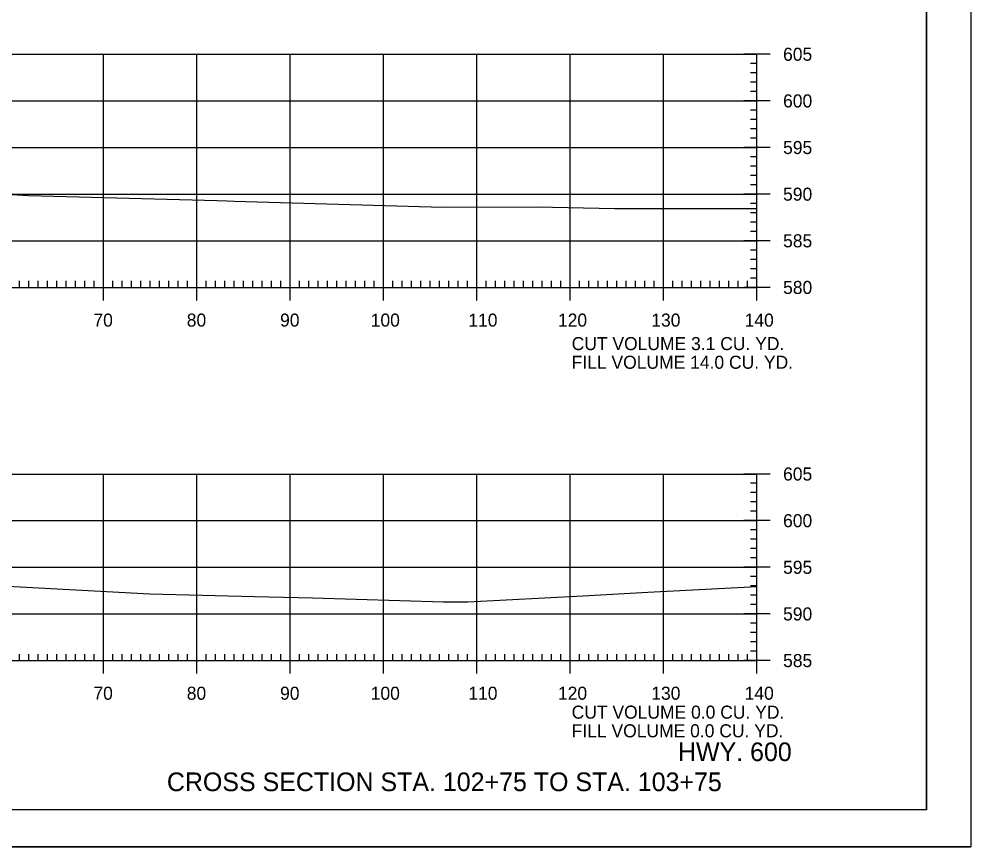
# Model space of a CAD drawing. Extents: x 961436 to 1372525, y 380079 to 2027791.
# Drawn here: x 1371255.8 to 1371357.8, y 380109.1 to 380197.8 of the extents above; entities that cross this region are included whole.
import ezdxf

# ---------------------------------------------------------------- set-up
doc = ezdxf.new("R2010")
doc.units = 0
for name, color, linetype in [('R_Axis', 7, 'Continuous'), ('R_Axis Annot', 7, 'Continuous'), ('R_Border', 7, 'Continuous'), ('R_Draft', 7, 'Continuous'), ('R_Exist Surface', 7, 'Continuous'), ('R_Grid', 7, 'Continuous'), ('R_No Plot', 7, 'Continuous')]:
    doc.layers.add(name, color=color, linetype=linetype)

msp = doc.modelspace()

# ---------------------------------------------------------------- linework, layer by layer
at = {"layer": 'R_Axis'}
for p, q in [((1371336.28, 380194.06), (1371333.48, 380194.06)), ((1371334.88, 380169.06), (1371334.88, 380194.06)), ((1371334.88, 380193.06), (1371334.18, 380193.06)), ((1371334.88, 380192.06), (1371334.18, 380192.06)), ((1371334.88, 380191.06), (1371334.18, 380191.06)), ((1371334.88, 380190.06), (1371334.18, 380190.06)), ((1371336.28, 380189.06), (1371333.48, 380189.06)), ((1371334.88, 380188.06), (1371334.18, 380188.06)), ((1371334.88, 380187.06), (1371334.18, 380187.06)), ((1371334.88, 380186.06), (1371334.18, 380186.06)), ((1371334.88, 380185.06), (1371334.18, 380185.06)), ((1371336.28, 380184.06), (1371333.48, 380184.06)), ((1371334.88, 380183.06), (1371334.18, 380183.06)), ((1371334.88, 380182.06), (1371334.18, 380182.06)), ((1371334.88, 380181.06), (1371334.18, 380181.06)), ((1371334.88, 380180.06), (1371334.18, 380180.06)), ((1371336.28, 380179.06), (1371333.48, 380179.06)), ((1371334.88, 380178.06), (1371334.18, 380178.06)), ((1371334.88, 380177.06), (1371334.18, 380177.06)), ((1371334.88, 380176.06), (1371334.18, 380176.06)), ((1371334.88, 380175.06), (1371334.18, 380175.06)), ((1371336.28, 380174.06), (1371333.48, 380174.06)), ((1371334.88, 380173.06), (1371334.18, 380173.06)), ((1371334.88, 380172.06), (1371334.18, 380172.06)), ((1371264.88, 380167.66), (1371264.88, 380170.46)), ((1371274.88, 380167.66), (1371274.88, 380170.46)), ((1371284.88, 380167.66), (1371284.88, 380170.46)), ((1371294.88, 380167.66), (1371294.88, 380170.46)), ((1371304.88, 380167.66), (1371304.88, 380170.46)), ((1371314.88, 380167.66), (1371314.88, 380170.46)), ((1371324.88, 380167.66), (1371324.88, 380170.46)), ((1371334.88, 380171.06), (1371334.18, 380171.06)), ((1371334.88, 380170.06), (1371334.18, 380170.06)), ((1371334.88, 380167.66), (1371334.88, 380170.46)), ((1371054.88, 380169.06), (1371334.88, 380169.06)), ((1371255.88, 380169.06), (1371255.88, 380169.76)), ((1371256.88, 380169.06), (1371256.88, 380169.76)), ((1371257.88, 380169.06), (1371257.88, 380169.76)), ((1371258.88, 380169.06), (1371258.88, 380169.76)), ((1371259.88, 380169.06), (1371259.88, 380169.76)), ((1371260.88, 380169.06), (1371260.88, 380169.76)), ((1371261.88, 380169.06), (1371261.88, 380169.76)), ((1371262.88, 380169.06), (1371262.88, 380169.76)), ((1371263.88, 380169.06), (1371263.88, 380169.76)), ((1371265.88, 380169.06), (1371265.88, 380169.76)), ((1371266.88, 380169.06), (1371266.88, 380169.76)), ((1371267.88, 380169.06), (1371267.88, 380169.76)), ((1371268.88, 380169.06), (1371268.88, 380169.76)), ((1371269.88, 380169.06), (1371269.88, 380169.76)), ((1371270.88, 380169.06), (1371270.88, 380169.76)), ((1371271.88, 380169.06), (1371271.88, 380169.76)), ((1371272.88, 380169.06), (1371272.88, 380169.76)), ((1371273.88, 380169.06), (1371273.88, 380169.76)), ((1371275.88, 380169.06), (1371275.88, 380169.76)), ((1371276.88, 380169.06), (1371276.88, 380169.76)), ((1371277.88, 380169.06), (1371277.88, 380169.76)), ((1371278.88, 380169.06), (1371278.88, 380169.76)), ((1371279.88, 380169.06), (1371279.88, 380169.76)), ((1371280.88, 380169.06), (1371280.88, 380169.76)), ((1371281.88, 380169.06), (1371281.88, 380169.76)), ((1371282.88, 380169.06), (1371282.88, 380169.76)), ((1371283.88, 380169.06), (1371283.88, 380169.76)), ((1371285.88, 380169.06), (1371285.88, 380169.76)), ((1371286.88, 380169.06), (1371286.88, 380169.76)), ((1371287.88, 380169.06), (1371287.88, 380169.76)), ((1371288.88, 380169.06), (1371288.88, 380169.76)), ((1371289.88, 380169.06), (1371289.88, 380169.76)), ((1371290.88, 380169.06), (1371290.88, 380169.76)), ((1371291.88, 380169.06), (1371291.88, 380169.76)), ((1371292.88, 380169.06), (1371292.88, 380169.76)), ((1371293.88, 380169.06), (1371293.88, 380169.76)), ((1371295.88, 380169.06), (1371295.88, 380169.76)), ((1371296.88, 380169.06), (1371296.88, 380169.76)), ((1371297.88, 380169.06), (1371297.88, 380169.76)), ((1371298.88, 380169.06), (1371298.88, 380169.76)), ((1371299.88, 380169.06), (1371299.88, 380169.76)), ((1371300.88, 380169.06), (1371300.88, 380169.76)), ((1371301.88, 380169.06), (1371301.88, 380169.76)), ((1371302.88, 380169.06), (1371302.88, 380169.76)), ((1371303.88, 380169.06), (1371303.88, 380169.76)), ((1371305.88, 380169.06), (1371305.88, 380169.76)), ((1371306.88, 380169.06), (1371306.88, 380169.76)), ((1371307.88, 380169.06), (1371307.88, 380169.76)), ((1371308.88, 380169.06), (1371308.88, 380169.76)), ((1371309.88, 380169.06), (1371309.88, 380169.76)), ((1371310.88, 380169.06), (1371310.88, 380169.76)), ((1371311.88, 380169.06), (1371311.88, 380169.76)), ((1371312.88, 380169.06), (1371312.88, 380169.76)), ((1371313.88, 380169.06), (1371313.88, 380169.76)), ((1371315.88, 380169.06), (1371315.88, 380169.76)), ((1371316.88, 380169.06), (1371316.88, 380169.76)), ((1371317.88, 380169.06), (1371317.88, 380169.76)), ((1371318.88, 380169.06), (1371318.88, 380169.76)), ((1371319.88, 380169.06), (1371319.88, 380169.76)), ((1371320.88, 380169.06), (1371320.88, 380169.76)), ((1371321.88, 380169.06), (1371321.88, 380169.76)), ((1371322.88, 380169.06), (1371322.88, 380169.76)), ((1371323.88, 380169.06), (1371323.88, 380169.76)), ((1371325.88, 380169.06), (1371325.88, 380169.76)), ((1371326.88, 380169.06), (1371326.88, 380169.76)), ((1371327.88, 380169.06), (1371327.88, 380169.76)), ((1371328.88, 380169.06), (1371328.88, 380169.76)), ((1371329.88, 380169.06), (1371329.88, 380169.76)), ((1371330.88, 380169.06), (1371330.88, 380169.76)), ((1371331.88, 380169.06), (1371331.88, 380169.76)), ((1371332.88, 380169.06), (1371332.88, 380169.76)), ((1371336.28, 380169.06), (1371333.48, 380169.06)), ((1371333.88, 380169.06), (1371333.88, 380169.76)), ((1371336.28, 380149.06), (1371333.48, 380149.06)), ((1371334.88, 380129.06), (1371334.88, 380149.06)), ((1371334.88, 380148.06), (1371334.18, 380148.06)), ((1371334.88, 380147.06), (1371334.18, 380147.06)), ((1371334.88, 380146.06), (1371334.18, 380146.06)), ((1371334.88, 380145.06), (1371334.18, 380145.06)), ((1371336.28, 380144.06), (1371333.48, 380144.06)), ((1371334.88, 380143.06), (1371334.18, 380143.06)), ((1371334.88, 380142.06), (1371334.18, 380142.06)), ((1371334.88, 380141.06), (1371334.18, 380141.06)), ((1371334.88, 380140.06), (1371334.18, 380140.06)), ((1371336.28, 380139.06), (1371333.48, 380139.06)), ((1371334.88, 380138.06), (1371334.18, 380138.06)), ((1371334.88, 380137.06), (1371334.18, 380137.06)), ((1371334.88, 380136.06), (1371334.18, 380136.06)), ((1371334.88, 380135.06), (1371334.18, 380135.06)), ((1371336.28, 380134.06), (1371333.48, 380134.06)), ((1371334.88, 380133.06), (1371334.18, 380133.06)), ((1371334.88, 380132.06), (1371334.18, 380132.06)), ((1371264.88, 380127.66), (1371264.88, 380130.46)), ((1371274.88, 380127.66), (1371274.88, 380130.46)), ((1371284.88, 380127.66), (1371284.88, 380130.46)), ((1371294.88, 380127.66), (1371294.88, 380130.46)), ((1371304.88, 380127.66), (1371304.88, 380130.46)), ((1371314.88, 380127.66), (1371314.88, 380130.46)), ((1371324.88, 380127.66), (1371324.88, 380130.46)), ((1371334.88, 380131.06), (1371334.18, 380131.06)), ((1371334.88, 380127.66), (1371334.88, 380130.46)), ((1371255.88, 380129.06), (1371255.88, 380129.76)), ((1371256.88, 380129.06), (1371256.88, 380129.76)), ((1371257.88, 380129.06), (1371257.88, 380129.76)), ((1371258.88, 380129.06), (1371258.88, 380129.76)), ((1371259.88, 380129.06), (1371259.88, 380129.76)), ((1371260.88, 380129.06), (1371260.88, 380129.76)), ((1371261.88, 380129.06), (1371261.88, 380129.76)), ((1371262.88, 380129.06), (1371262.88, 380129.76)), ((1371263.88, 380129.06), (1371263.88, 380129.76)), ((1371265.88, 380129.06), (1371265.88, 380129.76)), ((1371266.88, 380129.06), (1371266.88, 380129.76)), ((1371267.88, 380129.06), (1371267.88, 380129.76)), ((1371268.88, 380129.06), (1371268.88, 380129.76)), ((1371269.88, 380129.06), (1371269.88, 380129.76)), ((1371270.88, 380129.06), (1371270.88, 380129.76)), ((1371271.88, 380129.06), (1371271.88, 380129.76)), ((1371272.88, 380129.06), (1371272.88, 380129.76)), ((1371273.88, 380129.06), (1371273.88, 380129.76)), ((1371275.88, 380129.06), (1371275.88, 380129.76)), ((1371276.88, 380129.06), (1371276.88, 380129.76)), ((1371277.88, 380129.06), (1371277.88, 380129.76)), ((1371278.88, 380129.06), (1371278.88, 380129.76)), ((1371279.88, 380129.06), (1371279.88, 380129.76)), ((1371280.88, 380129.06), (1371280.88, 380129.76)), ((1371281.88, 380129.06), (1371281.88, 380129.76)), ((1371282.88, 380129.06), (1371282.88, 380129.76)), ((1371283.88, 380129.06), (1371283.88, 380129.76)), ((1371285.88, 380129.06), (1371285.88, 380129.76)), ((1371286.88, 380129.06), (1371286.88, 380129.76)), ((1371287.88, 380129.06), (1371287.88, 380129.76)), ((1371288.88, 380129.06), (1371288.88, 380129.76)), ((1371289.88, 380129.06), (1371289.88, 380129.76)), ((1371290.88, 380129.06), (1371290.88, 380129.76)), ((1371291.88, 380129.06), (1371291.88, 380129.76)), ((1371292.88, 380129.06), (1371292.88, 380129.76)), ((1371293.88, 380129.06), (1371293.88, 380129.76)), ((1371295.88, 380129.06), (1371295.88, 380129.76)), ((1371296.88, 380129.06), (1371296.88, 380129.76)), ((1371297.88, 380129.06), (1371297.88, 380129.76)), ((1371298.88, 380129.06), (1371298.88, 380129.76)), ((1371299.88, 380129.06), (1371299.88, 380129.76)), ((1371300.88, 380129.06), (1371300.88, 380129.76)), ((1371301.88, 380129.06), (1371301.88, 380129.76)), ((1371302.88, 380129.06), (1371302.88, 380129.76)), ((1371303.88, 380129.06), (1371303.88, 380129.76)), ((1371305.88, 380129.06), (1371305.88, 380129.76)), ((1371306.88, 380129.06), (1371306.88, 380129.76)), ((1371307.88, 380129.06), (1371307.88, 380129.76)), ((1371308.88, 380129.06), (1371308.88, 380129.76)), ((1371309.88, 380129.06), (1371309.88, 380129.76)), ((1371310.88, 380129.06), (1371310.88, 380129.76)), ((1371311.88, 380129.06), (1371311.88, 380129.76)), ((1371312.88, 380129.06), (1371312.88, 380129.76)), ((1371313.88, 380129.06), (1371313.88, 380129.76)), ((1371315.88, 380129.06), (1371315.88, 380129.76)), ((1371316.88, 380129.06), (1371316.88, 380129.76)), ((1371317.88, 380129.06), (1371317.88, 380129.76)), ((1371318.88, 380129.06), (1371318.88, 380129.76)), ((1371319.88, 380129.06), (1371319.88, 380129.76)), ((1371320.88, 380129.06), (1371320.88, 380129.76)), ((1371321.88, 380129.06), (1371321.88, 380129.76)), ((1371322.88, 380129.06), (1371322.88, 380129.76)), ((1371323.88, 380129.06), (1371323.88, 380129.76)), ((1371325.88, 380129.06), (1371325.88, 380129.76)), ((1371326.88, 380129.06), (1371326.88, 380129.76)), ((1371327.88, 380129.06), (1371327.88, 380129.76)), ((1371328.88, 380129.06), (1371328.88, 380129.76)), ((1371329.88, 380129.06), (1371329.88, 380129.76)), ((1371330.88, 380129.06), (1371330.88, 380129.76)), ((1371331.88, 380129.06), (1371331.88, 380129.76)), ((1371332.88, 380129.06), (1371332.88, 380129.76)), ((1371333.88, 380129.06), (1371333.88, 380129.76)), ((1371334.88, 380130.06), (1371334.18, 380130.06)), ((1371054.88, 380129.06), (1371334.88, 380129.06)), ((1371336.28, 380129.06), (1371333.48, 380129.06))]:
    msp.add_line(p, q, dxfattribs=at)
at = {"layer": 'R_Border'}
for q in [(1371353.06, 380318.52), (1371036.88, 380113.06)]:
    msp.add_line((1371353.06, 380113.06), q, dxfattribs=at)
at = {"layer": 'R_Exist Surface'}
for points in [[(1371252.57, 380179.15), (1371256.83, 380178.91), (1371277.06, 380178.37), (1371278.12, 380178.34), (1371278.87, 380178.32), (1371301.22, 380177.66), (1371311.35, 380177.71), (1371319.62, 380177.52), (1371327.03, 380177.52), (1371332.59, 380177.52), (1371334.88, 380177.51)], [(1371252.58, 380137.13), (1371269.83, 380136.22), (1371281.06, 380135.92), (1371287.28, 380135.78), (1371301.31, 380135.37), (1371303.92, 380135.34), (1371316.22, 380136), (1371323.2, 380136.38), (1371334.88, 380137)]]:
    msp.add_lwpolyline(points, dxfattribs=at)
at = {"layer": 'R_Grid'}
for p, q in [((1371054.88, 380194.06), (1371334.88, 380194.06)), ((1371264.88, 380169.06), (1371264.88, 380194.06)), ((1371274.88, 380169.06), (1371274.88, 380194.06)), ((1371284.88, 380169.06), (1371284.88, 380194.06)), ((1371294.88, 380169.06), (1371294.88, 380194.06)), ((1371304.88, 380169.06), (1371304.88, 380194.06)), ((1371314.88, 380169.06), (1371314.88, 380194.06)), ((1371324.88, 380169.06), (1371324.88, 380194.06)), ((1371334.88, 380169.06), (1371334.88, 380194.06)), ((1371054.88, 380189.06), (1371334.88, 380189.06)), ((1371054.88, 380184.06), (1371334.88, 380184.06)), ((1371054.88, 380179.06), (1371334.88, 380179.06)), ((1371054.88, 380174.06), (1371334.88, 380174.06)), ((1371054.88, 380169.06), (1371334.88, 380169.06)), ((1371054.88, 380149.06), (1371334.88, 380149.06)), ((1371264.88, 380129.06), (1371264.88, 380149.06)), ((1371274.88, 380129.06), (1371274.88, 380149.06)), ((1371284.88, 380129.06), (1371284.88, 380149.06)), ((1371294.88, 380129.06), (1371294.88, 380149.06)), ((1371304.88, 380129.06), (1371304.88, 380149.06)), ((1371314.88, 380129.06), (1371314.88, 380149.06)), ((1371324.88, 380129.06), (1371324.88, 380149.06)), ((1371334.88, 380129.06), (1371334.88, 380149.06)), ((1371054.88, 380144.06), (1371334.88, 380144.06)), ((1371054.88, 380139.06), (1371334.88, 380139.06)), ((1371054.88, 380134.06), (1371334.88, 380134.06)), ((1371054.88, 380129.06), (1371334.88, 380129.06))]:
    msp.add_line(p, q, dxfattribs=at)
at = {"layer": 'R_No Plot'}
msp.add_line((1371024.48, 380109.08), (1371357.81, 380109.08), dxfattribs=at)
for points in [[(1371024.47, 380322.41), (1371357.81, 380322.41), (1371357.81, 380109.08), (1371024.47, 380109.08)], [(1371270.8, 380318.52), (1371290.42, 380318.52), (1371290.42, 380308.64), (1371306.53, 380308.64), (1371329.73, 380308.64), (1371329.85, 380280.48), (1371353.06, 380280.48), (1371353.06, 380113.06), (1371036.88, 380113.06), (1371036.88, 380318.52)]]:
    msp.add_lwpolyline(points, close=True, dxfattribs=at)

# ---------------------------------------------------------------- texts
at = {"layer": 'R_Axis Annot'}
for s, p in [('605', (1371337.68, 380193.36)), ('600', (1371337.68, 380188.36)), ('595', (1371337.68, 380183.36)), ('590', (1371337.68, 380178.36)), ('585', (1371337.68, 380173.36)), ('580', (1371337.68, 380168.36)), ('70', (1371263.79, 380164.86)), ('80', (1371273.79, 380164.86)), ('90', (1371283.79, 380164.86)), ('100', (1371293.5, 380164.86)), ('110', (1371303.96, 380164.86)), ('120', (1371313.56, 380164.86)), ('130', (1371323.56, 380164.86)), ('140', (1371333.56, 380164.86)), ('CUT VOLUME 3.1 CU. YD.', (1371315.03, 380162.34)), ('FILL VOLUME 14.0 CU. YD.', (1371315.03, 380160.34)), ('605', (1371337.68, 380148.36)), ('600', (1371337.68, 380143.36)), ('595', (1371337.68, 380138.36)), ('590', (1371337.68, 380133.36)), ('585', (1371337.68, 380128.36)), ('70', (1371263.79, 380124.86)), ('80', (1371273.79, 380124.86)), ('90', (1371283.79, 380124.86)), ('100', (1371293.5, 380124.86)), ('110', (1371303.96, 380124.86)), ('120', (1371313.56, 380124.86)), ('130', (1371323.56, 380124.86)), ('140', (1371333.56, 380124.86)), ('CUT VOLUME 0.0 CU. YD.', (1371315.03, 380122.83)), ('FILL VOLUME 0.0 CU. YD.', (1371315.03, 380120.83))]:
    msp.add_text(s, height=1.4, dxfattribs=at).set_placement(p)
at = {"layer": 'R_Draft'}
for s, p in [('HWY. 600', (1371326.42, 380118.28)), ('CROSS SECTION STA. 102+75 TO STA. 103+75', (1371271.66, 380115.06))]:
    msp.add_text(s, height=2, dxfattribs=at).set_placement(p)

doc.saveas('drawing.dxf')
